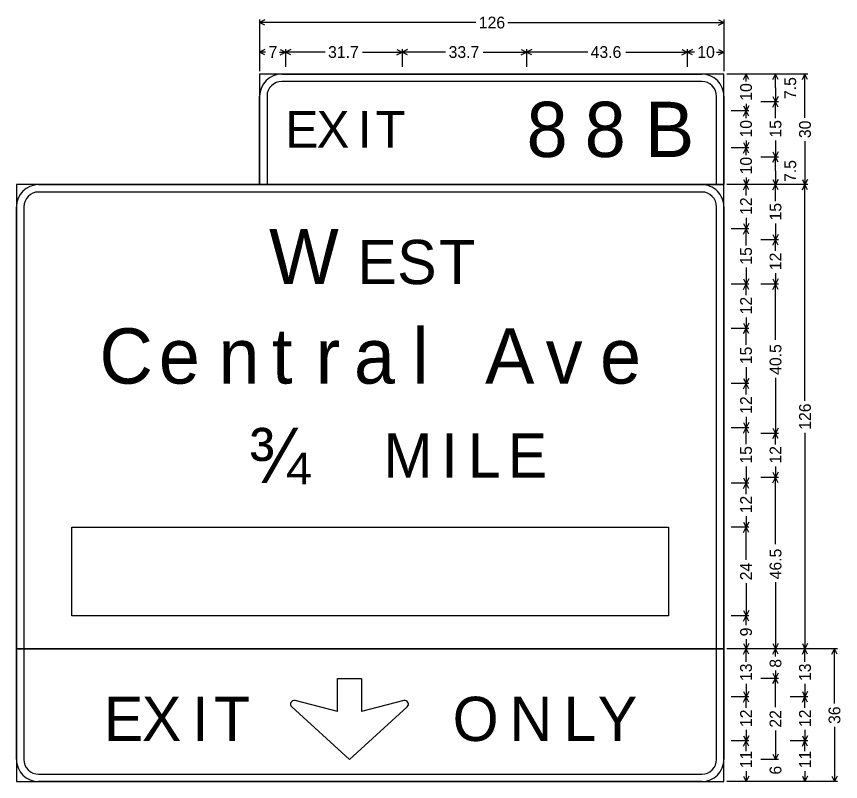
# Model space of a CAD drawing. Extents: x 667331 to 731245, y 738830 to 753817.
# Drawn here: x 719819.9 to 720155.4, y 747977.9 to 748289.4 of the extents above; entities that cross this region are included whole.
import ezdxf

# ---------------------------------------------------------------- set-up
doc = ezdxf.new("R2010")
doc.units = 0
doc.layers.add('R_SIGN', color=7, linetype='Continuous')

msp = doc.modelspace()

# ---------------------------------------------------------------- linework, layer by layer
at = {"layer": 'R_SIGN'}
for p, q in [((719918.9, 748288.1), (719918.9, 748267.1)), ((719921.05, 748287.97), (719918.9, 748286.9)), ((720006.91, 748286.9), (719918.9, 748286.9)), ((719921.05, 748285.82), (719918.9, 748286.9)), ((720019.89, 748286.9), (720107.9, 748286.9)), ((720105.76, 748287.97), (720107.9, 748286.9)), ((720105.76, 748285.82), (720107.9, 748286.9)), ((720107.9, 748288.1), (720107.9, 748267.1)), ((719918.9, 748276.1), (719918.9, 748268.9)), ((719921.05, 748275.97), (719918.9, 748274.9)), ((719927.26, 748275.97), (719929.4, 748274.9)), ((719929.4, 748276.1), (719929.4, 748268.9)), ((719931.55, 748275.97), (719929.4, 748274.9)), ((719974.81, 748275.97), (719976.95, 748274.9)), ((719976.95, 748276.1), (719976.95, 748268.9)), ((719979.1, 748275.97), (719976.95, 748274.9)), ((720025.42, 748275.97), (720027.56, 748274.9)), ((720027.56, 748276.1), (720027.56, 748268.9)), ((720029.71, 748275.97), (720027.56, 748274.9)), ((720090.76, 748275.97), (720092.9, 748274.9)), ((720092.9, 748276.1), (720092.9, 748268.9)), ((720092.9, 748276.1), (720092.9, 748268.9)), ((720095.05, 748275.97), (720092.9, 748274.9)), ((720105.76, 748275.97), (720107.9, 748274.9)), ((720107.9, 748276.1), (720107.9, 748268.9)), ((719921.33, 748274.9), (719918.9, 748274.9)), ((719921.05, 748273.82), (719918.9, 748274.9)), ((719926.97, 748274.9), (719929.4, 748274.9)), ((719927.26, 748273.82), (719929.4, 748274.9)), ((719945.54, 748274.9), (719929.4, 748274.9)), ((719931.55, 748273.82), (719929.4, 748274.9)), ((719960.81, 748274.9), (719976.95, 748274.9)), ((719974.81, 748273.82), (719976.95, 748274.9)), ((719994.62, 748274.9), (719976.95, 748274.9)), ((719979.1, 748273.82), (719976.95, 748274.9)), ((720009.89, 748274.9), (720027.56, 748274.9)), ((720025.42, 748273.82), (720027.56, 748274.9)), ((720052.45, 748274.9), (720027.56, 748274.9)), ((720029.71, 748273.82), (720027.56, 748274.9)), ((720068.02, 748274.9), (720092.9, 748274.9)), ((720090.76, 748273.82), (720092.9, 748274.9)), ((720095.87, 748274.9), (720092.9, 748274.9)), ((720095.05, 748273.82), (720092.9, 748274.9)), ((720104.93, 748274.9), (720107.9, 748274.9)), ((720105.76, 748273.82), (720107.9, 748274.9)), ((720142.1, 748265.9), (720109.1, 748265.9)), ((720118.1, 748265.9), (720110.9, 748265.9)), ((720115.83, 748263.75), (720116.9, 748265.9)), ((720116.9, 748262.93), (720116.9, 748265.9)), ((720117.98, 748263.75), (720116.9, 748265.9)), ((720130.1, 748265.9), (720122.9, 748265.9)), ((720127.83, 748263.75), (720128.9, 748265.9)), ((720128.9, 748260.27), (720128.9, 748265.9)), ((720129.98, 748263.75), (720128.9, 748265.9)), ((720139.83, 748263.75), (720140.9, 748265.9)), ((720140.9, 748248.14), (720140.9, 748265.9)), ((720141.98, 748263.75), (720140.9, 748265.9)), ((720128.9, 748260.27), (720128.9, 748254.65)), ((720127.83, 748256.79), (720128.9, 748254.65)), ((720129.98, 748256.79), (720128.9, 748254.65)), ((720115.83, 748253.04), (720116.9, 748250.9)), ((720116.9, 748253.87), (720116.9, 748250.9)), ((720117.98, 748253.04), (720116.9, 748250.9)), ((720130.1, 748254.65), (720122.9, 748254.65)), ((720127.83, 748252.5), (720128.9, 748254.65)), ((720128.9, 748247.94), (720128.9, 748254.65)), ((720129.98, 748252.5), (720128.9, 748254.65)), ((720118.1, 748250.9), (720110.9, 748250.9)), ((720115.83, 748248.75), (720116.9, 748250.9)), ((720116.9, 748247.93), (720116.9, 748250.9)), ((720117.98, 748248.75), (720116.9, 748250.9)), ((720116.9, 748238.87), (720116.9, 748235.9)), ((720128.9, 748238.86), (720128.9, 748232.15)), ((720140.9, 748238.65), (720140.9, 748220.9)), ((720118.1, 748235.9), (720110.9, 748235.9)), ((720118.1, 748235.9), (720110.9, 748235.9)), ((720115.83, 748238.04), (720116.9, 748235.9)), ((720115.83, 748233.75), (720116.9, 748235.9)), ((720117.98, 748238.04), (720116.9, 748235.9)), ((720116.9, 748232.93), (720116.9, 748235.9)), ((720117.98, 748233.75), (720116.9, 748235.9)), ((720130.1, 748232.15), (720122.9, 748232.15)), ((720130.1, 748232.15), (720122.9, 748232.15)), ((720127.83, 748234.29), (720128.9, 748232.15)), ((720127.83, 748230), (720128.9, 748232.15)), ((720129.98, 748234.29), (720128.9, 748232.15)), ((720128.9, 748226.52), (720128.9, 748232.15)), ((720129.98, 748230), (720128.9, 748232.15)), ((720128.9, 748226.52), (720128.9, 748220.9)), ((720115.83, 748223.04), (720116.9, 748220.9)), ((720116.9, 748223.87), (720116.9, 748220.9)), ((720117.98, 748223.04), (720116.9, 748220.9)), ((720127.83, 748223.04), (720128.9, 748220.9)), ((720129.98, 748223.04), (720128.9, 748220.9)), ((720139.83, 748223.04), (720140.9, 748220.9)), ((720141.98, 748223.04), (720140.9, 748220.9)), ((720142.1, 748220.9), (720109.1, 748220.9)), ((720142.1, 748220.9), (720109.1, 748220.9)), ((720118.1, 748220.9), (720110.9, 748220.9)), ((720118.1, 748220.9), (720110.9, 748220.9)), ((720115.83, 748218.75), (720116.9, 748220.9)), ((720116.9, 748216.42), (720116.9, 748220.9)), ((720117.98, 748218.75), (720116.9, 748220.9)), ((720130.1, 748220.9), (720122.9, 748220.9)), ((720130.1, 748220.9), (720122.9, 748220.9)), ((720127.83, 748218.75), (720128.9, 748220.9)), ((720128.9, 748214.19), (720128.9, 748220.9)), ((720129.98, 748218.75), (720128.9, 748220.9)), ((720139.83, 748218.75), (720140.9, 748220.9)), ((720140.9, 748132.89), (720140.9, 748220.9)), ((720141.98, 748218.75), (720140.9, 748220.9)), ((720115.83, 748205.04), (720116.9, 748202.9)), ((720116.9, 748207.38), (720116.9, 748202.9)), ((720117.98, 748205.04), (720116.9, 748202.9)), ((720128.9, 748205.11), (720128.9, 748198.4)), ((720118.1, 748202.9), (720110.9, 748202.9)), ((720115.83, 748200.75), (720116.9, 748202.9)), ((720116.9, 748196.19), (720116.9, 748202.9)), ((720117.98, 748200.75), (720116.9, 748202.9)), ((720130.1, 748198.4), (720122.9, 748198.4)), ((720127.83, 748200.54), (720128.9, 748198.4)), ((720127.83, 748196.25), (720128.9, 748198.4)), ((720129.98, 748200.54), (720128.9, 748198.4)), ((720128.9, 748193.92), (720128.9, 748198.4)), ((720129.98, 748196.25), (720128.9, 748198.4)), ((720116.9, 748187.11), (720116.9, 748180.4)), ((720128.9, 748184.88), (720128.9, 748180.4)), ((720115.83, 748182.54), (720116.9, 748180.4)), ((720117.98, 748182.54), (720116.9, 748180.4)), ((720127.83, 748182.54), (720128.9, 748180.4)), ((720129.98, 748182.54), (720128.9, 748180.4)), ((720118.1, 748180.4), (720110.9, 748180.4)), ((720115.83, 748178.25), (720116.9, 748180.4)), ((720116.9, 748175.92), (720116.9, 748180.4)), ((720117.98, 748178.25), (720116.9, 748180.4)), ((720130.1, 748180.4), (720122.9, 748180.4)), ((720127.83, 748178.25), (720128.9, 748180.4)), ((720128.9, 748157.78), (720128.9, 748180.4)), ((720129.98, 748178.25), (720128.9, 748180.4)), ((720115.83, 748164.54), (720116.9, 748162.4)), ((720116.9, 748166.88), (720116.9, 748162.4)), ((720117.98, 748164.54), (720116.9, 748162.4)), ((720118.1, 748162.4), (720110.9, 748162.4)), ((720115.83, 748160.25), (720116.9, 748162.4)), ((720116.9, 748155.69), (720116.9, 748162.4)), ((720117.98, 748160.25), (720116.9, 748162.4)), ((720116.9, 748146.61), (720116.9, 748139.9)), ((720115.83, 748142.04), (720116.9, 748139.9)), ((720117.98, 748142.04), (720116.9, 748139.9)), ((720128.9, 748142.26), (720128.9, 748119.65)), ((720118.1, 748139.9), (720110.9, 748139.9)), ((720115.83, 748137.75), (720116.9, 748139.9)), ((720116.9, 748135.42), (720116.9, 748139.9)), ((720117.98, 748137.75), (720116.9, 748139.9)), ((720116.9, 748126.38), (720116.9, 748121.9)), ((720118.1, 748121.9), (720110.9, 748121.9)), ((720115.83, 748124.04), (720116.9, 748121.9)), ((720115.83, 748119.75), (720116.9, 748121.9)), ((720117.98, 748124.04), (720116.9, 748121.9)), ((720116.9, 748115.19), (720116.9, 748121.9)), ((720117.98, 748119.75), (720116.9, 748121.9)), ((720127.83, 748121.79), (720128.9, 748119.65)), ((720129.98, 748121.79), (720128.9, 748119.65)), ((720130.1, 748119.65), (720122.9, 748119.65)), ((720127.83, 748117.5), (720128.9, 748119.65)), ((720128.9, 748115.17), (720128.9, 748119.65)), ((720129.98, 748117.5), (720128.9, 748119.65)), ((720140.9, 748119.91), (720140.9, 748031.9)), ((720116.9, 748106.11), (720116.9, 748099.4)), ((720128.9, 748106.13), (720128.9, 748101.65)), ((720115.83, 748101.54), (720116.9, 748099.4)), ((720117.98, 748101.54), (720116.9, 748099.4)), ((720130.1, 748101.65), (720122.9, 748101.65)), ((720130.1, 748101.65), (720122.9, 748101.65)), ((720127.83, 748103.79), (720128.9, 748101.65)), ((720127.83, 748099.5), (720128.9, 748101.65)), ((720129.98, 748103.79), (720128.9, 748101.65)), ((720128.9, 748074.53), (720128.9, 748101.65)), ((720129.98, 748099.5), (720128.9, 748101.65)), ((720118.1, 748099.4), (720110.9, 748099.4)), ((720115.83, 748097.25), (720116.9, 748099.4)), ((720116.9, 748094.92), (720116.9, 748099.4)), ((720117.98, 748097.25), (720116.9, 748099.4)), ((720116.9, 748085.88), (720116.9, 748081.4)), ((719842.4, 748045.4), (719842.4, 748081.4)), ((719842.4, 748081.4), (720085.4, 748081.4)), ((720085.4, 748081.4), (720085.4, 748045.4)), ((720118.1, 748081.4), (720110.9, 748081.4)), ((720115.83, 748083.54), (720116.9, 748081.4)), ((720115.83, 748079.25), (720116.9, 748081.4)), ((720117.98, 748083.54), (720116.9, 748081.4)), ((720116.9, 748068.18), (720116.9, 748081.4)), ((720117.98, 748079.25), (720116.9, 748081.4)), ((720116.9, 748058.62), (720116.9, 748045.4)), ((720128.9, 748059.01), (720128.9, 748031.9)), ((720115.83, 748047.54), (720116.9, 748045.4)), ((720117.98, 748047.54), (720116.9, 748045.4)), ((720085.4, 748045.4), (719842.4, 748045.4)), ((720118.1, 748045.4), (720110.9, 748045.4)), ((720118.1, 748045.4), (720110.9, 748045.4)), ((720115.83, 748043.25), (720116.9, 748045.4)), ((720116.9, 748041.49), (720116.9, 748045.4)), ((720117.98, 748043.25), (720116.9, 748045.4)), ((720115.83, 748034.04), (720116.9, 748031.9)), ((720116.9, 748035.8), (720116.9, 748031.9)), ((720117.98, 748034.04), (720116.9, 748031.9)), ((720127.83, 748034.04), (720128.9, 748031.9)), ((720129.98, 748034.04), (720128.9, 748031.9)), ((720139.83, 748034.04), (720140.9, 748031.9)), ((720141.98, 748034.04), (720140.9, 748031.9)), ((720142.1, 748031.9), (720109.1, 748031.9)), ((720154.1, 748031.9), (720109.1, 748031.9)), ((720118.1, 748031.9), (720110.9, 748031.9)), ((720118.1, 748031.9), (720110.9, 748031.9)), ((720115.83, 748029.75), (720116.9, 748031.9)), ((720116.9, 748026.69), (720116.9, 748031.9)), ((720117.98, 748029.75), (720116.9, 748031.9)), ((720130.1, 748031.9), (720122.9, 748031.9)), ((720130.1, 748031.9), (720122.9, 748031.9)), ((720127.83, 748029.75), (720128.9, 748031.9)), ((720128.9, 748028.76), (720128.9, 748031.9)), ((720129.98, 748029.75), (720128.9, 748031.9)), ((720142.1, 748031.9), (720134.9, 748031.9)), ((720139.83, 748029.75), (720140.9, 748031.9)), ((720140.9, 748026.69), (720140.9, 748031.9)), ((720141.98, 748029.75), (720140.9, 748031.9)), ((720151.83, 748029.75), (720152.9, 748031.9)), ((720152.9, 748009.68), (720152.9, 748031.9)), ((720153.98, 748029.75), (720152.9, 748031.9)), ((720127.83, 748022.04), (720128.9, 748019.9)), ((720128.9, 748023.04), (720128.9, 748019.9)), ((720129.98, 748022.04), (720128.9, 748019.9)), ((720116.9, 748017.61), (720116.9, 748012.4)), ((720130.1, 748019.9), (720122.9, 748019.9)), ((720127.83, 748017.75), (720128.9, 748019.9)), ((720128.9, 748008.18), (720128.9, 748019.9)), ((720129.98, 748017.75), (720128.9, 748019.9)), ((720140.9, 748017.61), (720140.9, 748012.4)), ((720115.83, 748014.54), (720116.9, 748012.4)), ((720117.98, 748014.54), (720116.9, 748012.4)), ((720139.83, 748014.54), (720140.9, 748012.4)), ((720141.98, 748014.54), (720140.9, 748012.4)), ((720118.1, 748012.4), (720110.9, 748012.4)), ((720115.83, 748010.25), (720116.9, 748012.4)), ((720116.9, 748007.92), (720116.9, 748012.4)), ((720117.98, 748010.25), (720116.9, 748012.4)), ((720142.1, 748012.4), (720134.9, 748012.4)), ((720139.83, 748010.25), (720140.9, 748012.4)), ((720140.9, 748007.92), (720140.9, 748012.4)), ((720141.98, 748010.25), (720140.9, 748012.4)), ((720152.9, 748000.12), (720152.9, 747977.9)), ((720116.9, 747998.88), (720116.9, 747994.4)), ((720128.9, 747998.62), (720128.9, 747986.9)), ((720140.9, 747998.88), (720140.9, 747994.4)), ((720118.1, 747994.4), (720110.9, 747994.4)), ((720118.1, 747994.4), (720110.9, 747994.4)), ((720115.83, 747996.54), (720116.9, 747994.4)), ((720115.83, 747992.25), (720116.9, 747994.4)), ((720117.98, 747996.54), (720116.9, 747994.4)), ((720116.9, 747990.2), (720116.9, 747994.4)), ((720117.98, 747992.25), (720116.9, 747994.4)), ((720142.1, 747994.4), (720134.9, 747994.4)), ((720142.1, 747994.4), (720134.9, 747994.4)), ((720139.83, 747996.54), (720140.9, 747994.4)), ((720139.83, 747992.25), (720140.9, 747994.4)), ((720141.98, 747996.54), (720140.9, 747994.4)), ((720140.9, 747990.2), (720140.9, 747994.4)), ((720141.98, 747992.25), (720140.9, 747994.4)), ((720130.1, 747986.9), (720122.9, 747986.9)), ((720130.1, 747986.9), (720122.9, 747986.9)), ((720127.83, 747989.04), (720128.9, 747986.9)), ((720129.98, 747989.04), (720128.9, 747986.9)), ((720115.83, 747980.04), (720116.9, 747977.9)), ((720116.9, 747982.09), (720116.9, 747977.9)), ((720117.98, 747980.04), (720116.9, 747977.9)), ((720139.83, 747980.04), (720140.9, 747977.9)), ((720140.9, 747982.09), (720140.9, 747977.9)), ((720141.98, 747980.04), (720140.9, 747977.9)), ((720151.83, 747980.04), (720152.9, 747977.9)), ((720153.98, 747980.04), (720152.9, 747977.9)), ((720154.1, 747977.9), (720109.1, 747977.9)), ((720118.1, 747977.9), (720110.9, 747977.9)), ((720130.1, 747977.9), (720122.9, 747977.9)), ((720142.1, 747977.9), (720134.9, 747977.9))]:
    msp.add_line(p, q, dxfattribs=at)
for points in [[(719918.9, 748220.9), (720107.9, 748220.9), (720107.9, 748265.9), (719918.9, 748265.9), (719918.9, 748220.9), (719918.9, 748220.9)], [(719927.9, 748265.9), (720098.9, 748265.9)], [(720098.9, 748262.9), (719927.9, 748262.9)], [(719918.9, 748220.9), (719918.9, 748256.9)], [(719921.9, 748256.9), (719921.9, 748220.9)], [(720104.9, 748220.9), (720104.9, 748256.9)], [(720107.9, 748256.9), (720107.9, 748220.9)], [(719819.9, 748031.9), (720107.9, 748031.9), (720107.9, 748220.9), (719819.9, 748220.9), (719819.9, 748031.9), (719819.9, 748031.9)], [(719828.9, 748220.9), (720098.9, 748220.9)], [(720098.9, 748217.9), (719828.9, 748217.9)], [(719819.9, 748031.9), (719819.9, 748211.9)], [(719822.9, 748211.9), (719822.9, 748031.9)], [(720104.9, 748031.9), (720104.9, 748211.9)], [(720107.9, 748211.9), (720107.9, 748031.9)], [(719819.9, 747977.9), (720107.9, 747977.9), (720107.9, 748031.9), (719819.9, 748031.9), (719819.9, 747977.9), (719819.9, 747977.9)], [(719819.9, 747986.9), (719819.9, 748031.9)], [(719822.9, 748031.9), (719822.9, 747986.9)], [(720104.9, 747986.9), (720104.9, 748031.9)], [(720107.9, 748031.9), (720107.9, 747986.9)], [(719950.59, 748019.9), (719960.34, 748019.9), (719960.34, 748006.4)], [(719950.59, 748006.4), (719950.59, 748019.9), (719950.59, 748019.9)], [(719950.59, 748006.4), (719933.34, 748010.85)], [(719977.59, 748010.85), (719960.34, 748006.4)], [(719931.94, 748008.3), (719955.46, 747986.9), (719955.46, 747986.9)], [(719955.46, 747986.9), (719978.98, 748008.3)], [(719828.9, 747980.9), (720098.9, 747980.9)], [(720098.9, 747977.9), (719828.9, 747977.9)]]:
    msp.add_lwpolyline(points, dxfattribs=at)
for centre, radius, start, end in [((719927.9, 748256.9), 9, 90.0002, 179.9998), ((720098.9, 748256.9), 9, 0, 90.0002), ((719927.9, 748256.9), 6, 90.0002, 179.9998), ((720098.9, 748256.9), 6, 0, 90.0002), ((719828.9, 748211.9), 9, 90.0002, 179.9998), ((720098.9, 748211.9), 9, 0, 90.0002), ((719828.9, 748211.9), 6, 90.0002, 179.9998), ((720098.9, 748211.9), 6, 0, 90.0002), ((719932.96, 748009.4), 1.5, 75.5273, 226.9749), ((719977.96, 748009.4), 1.5, 313.0252, 104.4728), ((719828.9, 747986.9), 9, 179.9998, 270.0001), ((719828.9, 747986.9), 6, 179.9998, 270.0001), ((720098.9, 747986.9), 9, 270.0001, 0.0003), ((720098.9, 747986.9), 6, 270.0001, 0.0003)]:
    msp.add_arc(centre, radius, start, end, dxfattribs=at)

# ---------------------------------------------------------------- texts
for s, height, p in [('126', 4.8, (720008.11, 748284.5)), ('7', 4.8, (719922.53, 748272.5)), ('31.7', 4.8, (719946.74, 748272.5)), ('33.7', 4.8, (719995.82, 748272.5)), ('43.6', 4.8, (720053.65, 748272.5)), ('10', 4.8, (720097.07, 748272.5)), ('8', 22.5, (720027.56, 748232.15)), ('8', 22.5, (720051.21, 748232.15)), ('B', 22.5, (720075.74, 748232.15)), ('E', 15, (719929.4, 748235.9)), ('X', 15, (719942.08, 748235.9)), ('I', 15, (719958.85, 748235.9)), ('T', 15, (719966.02, 748235.9)), ('W', 22.5, (719922.71, 748180.4)), ('E', 18, (719958.71, 748180.4)), ('S', 18, (719974.88, 748180.4)), ('T', 18, (719991.97, 748180.4)), ('C', 22.5, (719853.69, 748139.9)), ('t', 22.5, (719923.86, 748139.9)), ('l', 22.5, (719981.06, 748139.9)), ('A', 22.5, (720010.68, 748139.9)), ('e', 22.5, (719877.84, 748139.9)), ('n', 22.5, (719902.12, 748139.9)), ('r', 22.5, (719941.66, 748139.9)), ('a', 22.5, (719957.29, 748139.9)), ('v', 22.5, (720035.34, 748139.9)), ('e', 22.5, (720057.46, 748139.9)), ('¾', 22.5, (719914.22, 748099.4)), ('M', 18, (719969.27, 748101.65)), ('I', 18, (719992.86, 748101.65)), ('L', 18, (720003.64, 748101.65)), ('E', 18, (720019.91, 748101.65)), ('E', 18, (719855.5, 747994.4)), ('X', 18, (719870.95, 747994.4)), ('I', 18, (719891.39, 747994.4)), ('T', 18, (719900.34, 747994.4)), ('O', 18, (719997.46, 747994.4)), ('N', 18, (720020.65, 747994.4)), ('L', 18, (720042.61, 747994.4)), ('Y', 18, (720056.55, 747994.4))]:
    msp.add_text(s, height=height, dxfattribs=at).set_placement(p)
for s, p in [('10', (720119.3, 748255.07)), ('7.5', (720137.3, 748255.75)), ('10', (720119.3, 748240.07)), ('15', (720131.3, 748240.06)), ('30', (720143.3, 748239.85)), ('10', (720119.3, 748225.07)), ('7.5', (720137.3, 748222)), ('12', (720119.3, 748208.58)), ('15', (720131.3, 748206.31)), ('15', (720119.3, 748188.31)), ('12', (720131.3, 748186.08)), ('12', (720119.3, 748168.08)), ('15', (720119.3, 748147.81)), ('40.5', (720131.3, 748143.46)), ('12', (720119.3, 748127.58)), ('126', (720143.3, 748121.11)), ('15', (720119.3, 748107.31)), ('12', (720131.3, 748107.33)), ('12', (720119.3, 748087.08)), ('46.5', (720131.3, 748060.21)), ('24', (720119.3, 748059.82)), ('9', (720119.3, 748037)), ('8', (720131.3, 748024.24)), ('13', (720119.3, 748018.81)), ('13', (720143.3, 748018.81)), ('12', (720119.3, 748000.08)), ('12', (720143.3, 748000.08)), ('36', (720155.3, 748001.32)), ('22', (720131.3, 747999.82)), ('11', (720119.3, 747983.29)), ('11', (720143.3, 747983.29)), ('6', (720131.3, 747980.71))]:
    msp.add_text(s, height=4.8, rotation=90.0002, dxfattribs=at).set_placement(p)

doc.saveas('drawing.dxf')
